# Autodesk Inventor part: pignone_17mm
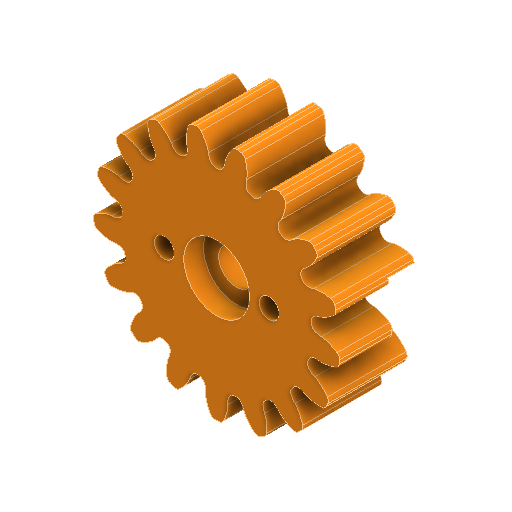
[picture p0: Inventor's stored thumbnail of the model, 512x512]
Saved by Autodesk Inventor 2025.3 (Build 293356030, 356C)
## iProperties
Created: 2026-01
Part Number: pignone_17mm
Material: Plastica ABS
Document SubType Name: Modeling
Designer: 18907419
Density: 1.06 g/cm^3
Appearance: Arancione
Author: 18907419
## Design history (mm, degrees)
sketch "Sketch1"
  geometry: C1 r 7.25 at (0, 0) reference; C2 r 7.987 at (0, 0) reference; C3 r 8.5 at (0, 0) reference; A1 r 9.5 centre (0, 0) between (-1.413, 9.394) and (1.413, 9.394) reference; 50 further points
  constraints: 4 centre point, 2 point on circle, 109 other
extrude "Estrusione1" join sketch "Sketch1" distance "d0" = 6 (= Larghezza_faccia); taper "d1" = 0 deg
extrude "Estrusione2" cut sketch "Sketch1" extent not by distance; stored distance "d2" = 0; taper "d3" = 0 deg
pattern_circular "Serie circolare1" dims angle "d5" = 360 deg
sketch "Schizzo2"
  geometry: C1 r 1.543 at (0, 0); 1 further point
  constraints: 1 centre point
sketch "Schizzo3"
  geometry: 2 further points
hole "Foro1" sketch "Schizzo3" at (0, 0) diameter "d7" = 2.7; stored, may be unused: countersink angle "d11" = 90 deg, drill point angle "d13" = 118 deg; dims "d8" = 6, "d9" = 5, "d10" = 1.5, "d12" = 8
extrude "Estrusione3" cut sketch "Schizzo5" distance "d24" = 2; taper "d25" = 0 deg
sketch "Schizzo6"
  geometry: C1 r 8.5 at (0, 0); 1 further point
  constraints: 1 centre point
  dimensions: "d26" = 17 diameter of C1
feature "SupEstrusione1" sketch "Schizzo6" dims "d27" = 10, "d28" = 0
sketch "Schizzo7"
  geometry: 3 further points
  constraints: 1 coincident, 3 other
extrude "Estrusione4" cut sketch "Schizzo7" distance "d29" = 0.5; taper "d30" = 0 deg
sketch "Schizzo8"
  geometry: C1 r 3.5 at (0, 0); 1 further point
  constraints: 1 centre point, 1 coincident
  dimensions: "d31" = 7 diameter of C1
extrude "Estrusione5" cut sketch "Schizzo8" distance "d32" = 1; taper "d33" = 0 deg
sketch "Schizzo9"
  geometry: C1 r 9.4 at (0, 0); A1 r 9.5 centre (0, 0) between (9.422, -1.212) and (9.485, -0.54) reference; 2 further points
  constraints: 1 centre point, 1 coincident, 3 other
  dimensions: "d36" = 0.1 dimension on C1
extrude "Estrusione6" cut sketch "Schizzo9" extent not by distance; stored distance "d37" = 0; taper "d38" = 0 deg
fillet "Raccordo1" dims "d39" = 0.4
pattern_circular "Serie circolare2" dims angle "d41" = 360 deg
sketch "Schizzo11"
  geometry: L1 (0, 0)-(-2.239, 0) reference; L2 (0, 0)-(0, -0.874) reference; L3 (-1.827, -3.05)-(-7.252, -2.661); L4 (-15.643, -1.995)-(-1.6, -3) reference; L5 (-1.827, 3.05)-(-9.052, 2.533); L6 (1.827, -3.05)-(7.252, -2.661); L7 (1.827, 3.05)-(9.052, 2.533); A1 r 9.4 centre (0, 0) between (9.083, 2.419) and (8.996, 2.725); A2 r 9.4 centre (0, 0) between (7.596, 5.537) and (7.404, 5.791); A3 r 9.4 centre (0, 0) between (5.083, 7.907) and (4.812, 8.075); A4 r 9.4 centre (0, 0) between (1.883, 9.209) and (1.571, 9.268); A5 r 9.4 centre (0, 0) between (-1.571, 9.268) and (-1.883, 9.209); A6 r 9.4 centre (0, 0) between (-4.812, 8.075) and (-5.083, 7.907); A7 r 9.4 centre (0, 0) between (-7.404, 5.791) and (-7.596, 5.537); A8 r 9.4 centre (0, 0) between (-8.996, 2.725) and (-9.083, 2.419); A9 r 9.4 centre (0, 0) between (-9.373, -0.709) and (-9.344, -1.026); A10 r 9.4 centre (0, 0) between (-8.484, -4.047) and (-8.342, -4.332); A11 r 9.4 centre (0, 0) between (-6.449, -6.838) and (-6.214, -7.053); A12 r 9.4 centre (0, 0) between (-3.544, -8.706) and (-3.247, -8.821); A13 r 9.4 centre (0, 0) between (-0.159, -9.399) and (0.159, -9.399); A14 r 9.4 centre (0, 0) between (3.247, -8.821) and (3.544, -8.706); A15 r 9.4 centre (0, 0) between (6.214, -7.053) and (6.449, -6.838); A16 r 9.4 centre (0, 0) between (8.342, -4.332) and (8.484, -4.047); A17 r 9.4 centre (0, 0) between (9.344, -1.026) and (9.373, -0.709); 75 further points
  constraints: 17 centre point, 12 end point, 6 symmetric about line, 2 horizontal, 2 point on circle, 2 point on line, 2 vertical, 1 coincident, 1 parallel, 176 other
extrude "Estrusione7" cut sketch "Schizzo11" distance "d43" = 2; taper "d44" = 0 deg
sketch "Schizzo12"
  geometry: C1 r 0.4 at (-6.3, 0) reference; C2 r 0.4 at (-4, 0) reference; C3 r 0.4 at (4, 0) reference; C4 r 0.4 at (6.3, 0) reference; 1 further point
hole "Foro3" sketch "Schizzo12" at (-4, 0), (4, 0) diameter "d45" = 1.5; stored, may be unused: countersink angle "d49" = 90 deg, drill point angle "d51" = 118 deg; dims "d46" = 6, "d47" = 5, "d48" = 1.5, "d50" = 8
node "Solido1"
node "Superf1"
node "Riferimento11"
node "Riferimento12"
node "Riferimento13"
node "Riferimento14"
node "Riferimento15"
other parameters: "Modulo" = 1 [user parameter], "Angolo_di_pressione" = 20 deg [user parameter], "Gioco_profilo_unità" = 2.5 [user parameter], "Raggio_circolare_unità" = 3.5 [user parameter], "Diametro_testa" = 19 [user parameter], "Diametro_di_fondo" = 14.5 [user parameter], "Diametro_di_base" = 15.97477 [user parameter], "Diametro_primitivo" = 17 [user parameter], "Larghezza_faccia" = 6 [user parameter; used in 1 equation term], "Angolo_elica" = 0 [user parameter], "Correzione_unità" = 0 [user parameter], "Modifica_aggiunta_unità" = 0 [user parameter], "Passo_circonferenziale" = 18 deg [user parameter], "Spostamento_strumento_gioco" = 0 [user parameter], "Spostamento_strumento_totale" = 0 [user parameter], "Interno" = 0 [user parameter], "d21" = 0.5, "d22" = 0.2, "d23" = 0.5
